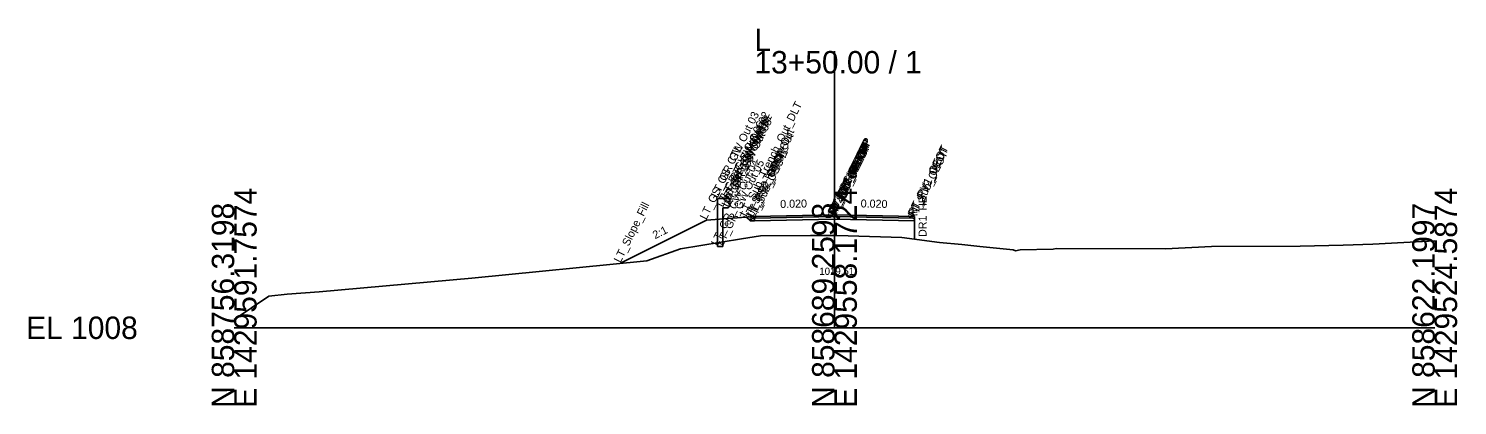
# Model space of a CAD drawing. Extents: x -26 to 153, y -10 to 13058.
# Drawn here: x -25.7 to 152.8, y 3990.3 to 4037.4 of the extents above; entities that cross this region are included whole.
import ezdxf

# ---------------------------------------------------------------- set-up
doc = ezdxf.new("R2010")
doc.units = 0
for name, color, linetype in [('Default', 7, 'Continuous'), ('Exist Cross Section Cell', 7, 'Continuous'), ('Exist XS Ground Line', 7, 'Continuous'), ('Prop CMT Guardrail Widen Shoulder', 7, 'Continuous'), ('Prop CMT Pvmt Course 1', 7, 'Continuous'), ('Prop CMT Pvmt Course 2', 7, 'Continuous'), ('Prop CMT Pvmt Surface', 7, 'Continuous'), ('Prop CMT Pvmt Surface Shoulder', 7, 'Continuous'), ('Prop CMT Shld Paved Course 1', 7, 'Continuous'), ('Prop CMT Shld Paved Course 2', 7, 'Continuous'), ('Prop CMT Slope Grass', 7, 'Continuous'), ('Prop CMT Subgrade Daylight Point', 7, 'Continuous'), ('Prop CMT Subgrade Earthwork', 7, 'Continuous'), ('Prop CMT Template Flag', 7, 'Continuous'), ('Prop XS Dump Level', 7, 'Continuous'), ('Prop XS SE Text', 7, 'Continuous'), ('Prop XS Side Slope Text', 7, 'Continuous'), ('Prop XSC Text', 7, 'Continuous')]:
    doc.layers.add(name, color=color, linetype=linetype)

msp = doc.modelspace()

# ---------------------------------------------------------------- linework, layer by layer
at = {"layer": 'Exist Cross Section Cell'}
for p, q in [((75, 4000), (75, 4034.56)), ((0, 4000), (75, 4000)), ((75, 4000), (150, 4000))]:
    msp.add_line(p, q, dxfattribs=at)
at = {"layer": 'Exist XS Ground Line'}
msp.add_lwpolyline([(0, 4001.03), (4.32, 4003.94), (6.62, 4004.19), (10.62, 4004.49), (29.71, 4006.2), (51.57, 4008.38), (55.75, 4009.87), (63.39, 4011.1), (65.78, 4011.47), (72.01, 4011.51), (74.2, 4011.52), (75, 4011.51), (76.73, 4011.49), (83.44, 4011.29), (88.12, 4010.63), (90.9, 4010.38), (93.17, 4010.15), (97.32, 4009.74), (97.62, 4009.61), (98.19, 4009.73), (102.31, 4009.81), (102.72, 4009.92), (116.38, 4009.86), (122.13, 4010.13), (133.17, 4010.2), (138.57, 4010.3), (142.28, 4010.46), (150, 4010.86)], dxfattribs=at)
at = {"layer": 'Prop CMT Guardrail Widen Shoulder'}
for points in [[(60.4, 4010.16), (60.4, 4016.16)], [(60.4, 4016.16), (61.73, 4016.16), (62, 4015.87)], [(62, 4015.28), (61.73, 4014.99), (61.06, 4014.99)], [(62, 4015.87), (61.73, 4015.57)], [(61.73, 4015.57), (62, 4015.28)], [(61.06, 4014.99), (61.06, 4010.16)], [(61.06, 4010.16), (60.4, 4010.16)]]:
    msp.add_lwpolyline(points, dxfattribs=at)
at = {"layer": 'Prop CMT Pvmt Course 1'}
for points in [[(75, 4014.1), (65, 4013.9)], [(65, 4013.9), (65, 4013.69)], [(65, 4013.69), (75, 4013.89)], [(75, 4013.89), (75, 4014.1)], [(75, 4014.1), (85, 4013.9)], [(75, 4013.89), (75, 4014.1)], [(85, 4013.69), (75, 4013.89)], [(85, 4013.9), (85, 4013.69)]]:
    msp.add_lwpolyline(points, dxfattribs=at)
msp.add_lwpolyline([(75, 4013.89), (75, 4013.97), (75, 4013.97), (75, 4013.89)], close=True, dxfattribs=at)
msp.add_lwpolyline([(75, 4013.89), (75, 4013.97), (75, 4013.97), (75, 4013.89)], close=True, dxfattribs=at)
at = {"layer": 'Prop CMT Pvmt Course 2'}
for points in [[(75, 4013.89), (65, 4013.69)], [(65, 4013.69), (65, 4013.36)], [(65, 4013.36), (75, 4013.56)], [(75, 4013.56), (75, 4013.89)], [(75, 4013.56), (75, 4013.89)], [(75, 4013.89), (85, 4013.69)], [(85, 4013.36), (75, 4013.56)], [(85, 4013.69), (85, 4013.36)]]:
    msp.add_lwpolyline(points, dxfattribs=at)
at = {"layer": 'Prop CMT Pvmt Surface'}
for points in [[(75, 4014.1), (65, 4013.9)], [(75, 4014.1), (85, 4013.9)]]:
    msp.add_lwpolyline(points, dxfattribs=at)
at = {"layer": 'Prop CMT Pvmt Surface Shoulder'}
msp.add_lwpolyline([(65, 4013.9), (65, 4013.9)], dxfattribs=at)
at = {"layer": 'Prop CMT Shld Paved Course 1'}
for points in [[(65, 4013.9), (64.79, 4013.68)], [(64.79, 4013.68), (65, 4013.69)], [(65, 4013.9), (65, 4013.9)], [(65, 4013.69), (65, 4013.9)]]:
    msp.add_lwpolyline(points, dxfattribs=at)
at = {"layer": 'Prop CMT Shld Paved Course 2'}
for points in [[(64.79, 4013.68), (64.45, 4013.34)], [(65, 4013.69), (64.79, 4013.68)], [(64.79, 4013.68), (64.79, 4013.68)], [(65, 4013.36), (65, 4013.69)], [(64.45, 4013.34), (65, 4013.36)]]:
    msp.add_lwpolyline(points, dxfattribs=at)
at = {"layer": 'Prop CMT Slope Grass'}
msp.add_lwpolyline([(65, 4013.9), (59, 4013.42), (48.27, 4008.05)], dxfattribs=at)
at = {"layer": 'Prop CMT Subgrade Earthwork'}
for points in [[(64.45, 4013.34), (63.98, 4013.82)], [(75, 4013.56), (65, 4013.36)], [(75, 4013.56), (85, 4013.36)], [(65, 4013.36), (64.45, 4013.34)]]:
    msp.add_lwpolyline(points, dxfattribs=at)
at = {"layer": 'Prop CMT Template Flag'}
msp.add_line((85, 4013.9), (85, 4011.07), dxfattribs=at)

# ---------------------------------------------------------------- texts
at = {"layer": 'Default'}
msp.add_text('-', height=0.0001, dxfattribs=at).set_placement((0, 4000))
at = {"layer": 'Exist Cross Section Cell'}
for s, p in [('L', (65, 4034.56)), ('13+50.00 / 1', (65, 4031.76)), ('EL 1008', (-26, 3998.6))]:
    msp.add_text(s, height=2.8, dxfattribs=at).set_placement(p)
for s, p in [('E 1429591.7574', (2.8, 3990)), ('E 1429558.1724', (77.8, 3990)), ('E 1429524.5874', (152.8, 3990)), ('N 858756.3198', (0, 3990)), ('N 858689.2598', (75, 3990)), ('N 858622.1997', (150, 3990))]:
    msp.add_text(s, height=2.8, rotation=90, dxfattribs=at).set_placement(p)
at = {"layer": 'Prop CMT Subgrade Daylight Point'}
msp.add_text('1019.51', height=0.9, dxfattribs=at).set_placement((73.11, 4006.61))
at = {"layer": 'Prop XS Dump Level'}
for s, p in [('LT_Sub_Trench_Out_DLT', (63.98, 4013.82)), ('LT_GR_GW Out 03', (60.4, 4016.16)), ('LT_GR_GW Out 02', (61.73, 4016.16)), ('LT_GR_GW Out 09', (61.73, 4015.57)), ('LT_GR_GW Out 01', (62, 4015.87)), ('LT_GR_GW Out 08', (62, 4015.28)), ('LT_GR_GW Out 06', (61.06, 4014.99)), ('LT_GR_GW Out 07', (61.73, 4014.99)), ('LT_Sub_Trench_Out', (64.45, 4013.34)), ('LT_PS2_Shelf_Out', (64.79, 4013.68)), ('LT_GS_OS_CTL', (59, 4013.42)), ('LT_PS2_OEOP', (64.79, 4013.68)), ('LT_PV1_OEOT', (65, 4013.9)), ('LT_PS1_OEOP', (65, 4013.9)), ('LT_PV2_OEOT', (65, 4013.69)), ('RT_PV1_OEEOP', (75, 4013.97)), ('RT_PV2_OEEOP', (75, 4013.89)), ('LT_PV1_OEEOP', (75, 4013.97)), ('LT_PV2_OEEOP', (75, 4013.89)), ('RT_Sub_OEEOP', (75, 4013.56)), ('RT_PV1_IEEOP', (75, 4013.97)), ('RT_PV2_IEEOP', (75, 4013.89)), ('LT_Sub_OEEOP', (75, 4013.56)), ('LT_PV1_IEEOP', (75, 4013.97)), ('LT_PV2_IEEOP', (75, 4013.89)), ('RT_PV1_OEOT', (85, 4013.9)), ('RT_PV2_OEOT', (85, 4013.69)), ('LT_GR_GW Out 04', (60.4, 4010.16)), ('LT_GR_GW Out 05', (61.06, 4010.16)), ('LT_Sub_OEOT', (65, 4013.36)), ('RT_Sub_OEOT', (85, 4013.36)), ('PV1_PGL', (75, 4014.1)), ('PV2_PGL', (75, 4013.89)), ('LT_Slope_Fill', (48.27, 4008.05))]:
    msp.add_text(s, height=1, rotation=63.5833, dxfattribs=at).set_placement(p)
at = {"layer": 'Prop XS SE Text'}
for rotation, p in [(1.1458, (68.23, 4014.96)), (358.8542, (78.27, 4015.03))]:
    msp.add_text('0.020', height=1, rotation=rotation, dxfattribs=at).set_placement(p)
at = {"layer": 'Prop XS Side Slope Text'}
msp.add_text('2:1', height=1, rotation=26.5651, dxfattribs=at).set_placement((52.59, 4011.05))
at = {"layer": 'Prop XSC Text'}
msp.add_text('DR1 TIE', height=1, rotation=90, dxfattribs=at).set_placement((86.51, 4011.34))

doc.saveas('drawing.dxf')
